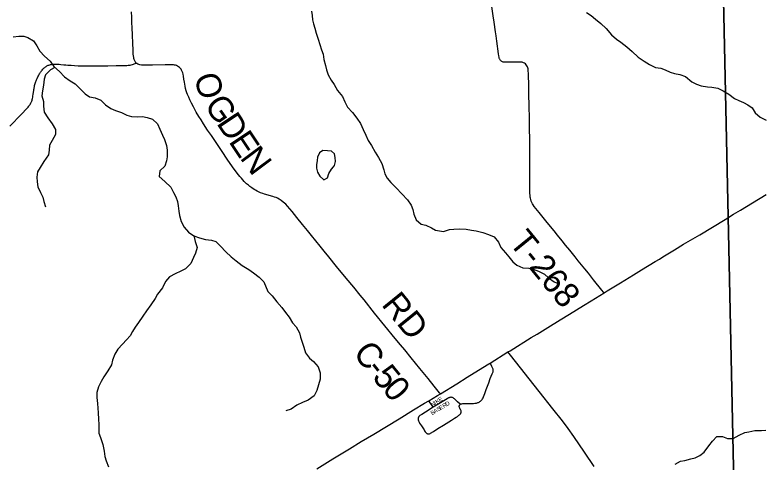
# Model space of a CAD drawing. Extents: x 1442749 to 1756758, y 235267 to 677782.
# Drawn here: x 1568709 to 1577781, y 515411 to 520821 of the extents above; entities that cross this region are included whole.
import ezdxf

# ---------------------------------------------------------------- set-up
doc = ezdxf.new("R2010")
doc.units = 0
for name, color, linetype in [('GM_X_County_Road', 7, 'Continuous'), ('GM_X_County_Road_Text', 7, 'Continuous'), ('GM_X_County_Subdivision', 7, 'Continuous'), ('GM_X_County_Subdivision_Text', 7, 'Continuous'), ('GM_X_Minor_Lake', 7, 'Continuous'), ('GM_X_Minor_River', 7, 'Continuous'), ('GM_X_State_Route', 7, 'Continuous'), ('GM_X_Township', 7, 'Continuous'), ('GM_X_Township_Road', 7, 'Continuous'), ('GM_X_Township_Road_Text', 7, 'Continuous')]:
    doc.layers.add(name, color=color, linetype=linetype)

msp = doc.modelspace()

# ---------------------------------------------------------------- linework, layer by layer
at = {"layer": 'GM_X_County_Road'}
for points in [[(1570179.2, 520236.9), (1570171.9, 520243.8), (1570162.8, 520256.4), (1570154.4, 520273.3), (1570150.9, 520282.3), (1570147.6, 520294.4), (1570145, 520307.3), (1570142.2, 520325.7), (1570140.5, 520346.1), (1570139.1, 520367.3), (1570137, 520409.6), (1570135, 520462.3), (1570133.4, 520500.4), (1570131.2, 520557), (1570129.7, 520588.2), (1570127, 520657.2), (1570123.7, 520739.7), (1570121.5, 520795.9), (1570119.3, 520857.7)], [(1573854.6, 516237.1), (1573845.8, 516247.9), (1573781.4, 516327.4), (1573705.3, 516421.3), (1573605.6, 516544), (1573553.3, 516608.4), (1573501.3, 516672), (1573423.8, 516767), (1573371.8, 516830.2), (1573308.8, 516905.8), (1573184.9, 517058.7), (1573059.9, 517214), (1572931.5, 517373.7), (1572884.3, 517431.4), (1572808.1, 517526), (1572715, 517637.9), (1572599.8, 517776.5), (1572503.8, 517895.7), (1572450.7, 517962.5), (1572401.5, 518024), (1572297.8, 518150.8), (1572248.5, 518212.1), (1572188.9, 518285.6), (1572120.4, 518370), (1572062.3, 518442), (1572035.5, 518473.7), (1572006.2, 518506.8), (1571984.3, 518530.5), (1571954.9, 518557.4), (1571928.4, 518577.4), (1571902.8, 518593), (1571884.8, 518602.5), (1571867.5, 518610.5), (1571848.7, 518617.8), (1571829.6, 518624.1), (1571812.3, 518629.2), (1571772.8, 518640), (1571729.1, 518652.5), (1571709, 518658.7), (1571678.5, 518669.8), (1571655.9, 518679.5), (1571638.9, 518687.8), (1571617.1, 518699.6), (1571600.4, 518709), (1571573, 518727.7), (1571551.9, 518743.7), (1571532.8, 518760), (1571511.3, 518779.7), (1571482.5, 518807.5), (1571447.5, 518844.9), (1571429.1, 518865.3), (1571412.5, 518886.9), (1571385.1, 518922.9), (1571341.8, 518982.3), (1571276.9, 519076.6), (1571215.3, 519168.1), (1571166.7, 519239.9), (1571084.3, 519361.6), (1571038.6, 519429.1), (1570990.1, 519504.1), (1570959.6, 519551.2), (1570934, 519593.1), (1570902.7, 519646.8), (1570868.1, 519709.7), (1570844.1, 519755.6), (1570824.3, 519795.8), (1570810.1, 519826.3), (1570797.3, 519858.2), (1570788.8, 519880.8), (1570781.7, 519901.2), (1570773.4, 519930.7), (1570766.4, 519960.9), (1570762.2, 519984.5), (1570758.1, 520009.1), (1570752.5, 520044.8), (1570746.7, 520081.2), (1570742.1, 520106.2), (1570738, 520121.4), (1570732.1, 520138.4), (1570724.8, 520153), (1570718.2, 520164.1), (1570708.9, 520176.6), (1570697.4, 520186.6), (1570686, 520195.4), (1570673.8, 520203.3), (1570663.8, 520207.8), (1570651.3, 520212), (1570638.5, 520215.1), (1570626.7, 520217.1), (1570614.2, 520217.8), (1570590.6, 520218.5), (1570561.5, 520218.9), (1570525.8, 520218.2), (1570374.5, 520215.4), (1570301, 520214), (1570264.3, 520214.4), (1570239, 520215.1), (1570220.3, 520216.8), (1570206.4, 520220.6), (1570196.1, 520225.1), (1570183, 520233.3), (1570179.2, 520236.9)], [(1575715.5, 515358.6), (1575599, 515528.7), (1575468.3, 515720.9), (1575399.6, 515816.9), (1575330, 515908.4), (1575214, 516055), (1575049.4, 516263.6), (1574702.5, 516704.5), (1574672.5, 516742.7)], [(1573768.5, 516072.9), (1573754.5, 516094.2), (1573723.7, 516141.1), (1573715.7, 516153.2)]]:
    msp.add_lwpolyline(points, dxfattribs=at)
at = {"layer": 'GM_X_County_Subdivision'}
for points in [[(1573768.5, 516072.9), (1573676.6, 516016.1), (1573629.2, 515987.5), (1573616, 515979.5), (1573607.8, 515973.9), (1573602.2, 515969.6), (1573597.4, 515965.2), (1573593, 515959.6), (1573590.9, 515956.1), (1573588.7, 515950.9), (1573587, 515946.6), (1573585.7, 515940.5), (1573585.2, 515936.1), (1573584.8, 515930.5), (1573585.2, 515924.9), (1573586.5, 515919.1), (1573588.3, 515913.1), (1573590.5, 515907.5), (1573593.5, 515901), (1573597.4, 515893.6), (1573603.4, 515883.2), (1573624.4, 515850.3), (1573656.8, 515798.9), (1573664.2, 515787.3), (1573671.5, 515776.3), (1573677.7, 515768.6), (1573682.7, 515763), (1573686.4, 515759.9), (1573689.8, 515757.3), (1573693.7, 515755.2), (1573699, 515753), (1573704.2, 515751.7), (1573708.9, 515751.3), (1573716.1, 515752.1), (1573722, 515753.9), (1573729.8, 515756.9), (1573736.3, 515760.4), (1573772.8, 515781.8), (1573825.7, 515814.9), (1573892.7, 515855.9), (1573926.4, 515876.7), (1573988.5, 515916.2), (1574026.2, 515940), (1574045.1, 515952.8), (1574060.5, 515963.5), (1574080, 515977.8), (1574087.4, 515983.9), (1574093.2, 515989), (1574097.8, 515994.7), (1574100.9, 515999.5), (1574102.9, 516004.3), (1574104.8, 516009.9), (1574105.4, 516015), (1574105.5, 516022.2), (1574104.5, 516029.4), (1574102.2, 516036.4), (1574098.7, 516045.1), (1574095.2, 516051.9), (1574090, 516062), (1574087, 516068.9), (1574084.8, 516075.1), (1574083.7, 516080.2), (1574083.5, 516084.6), (1574083.9, 516089.4), (1574085.2, 516093.7), (1574087.8, 516098.9), (1574091.7, 516104.5), (1574095.6, 516109.4), (1574100, 516111.9), (1574106.9, 516115), (1574113.5, 516116.7), (1574124.7, 516117.9), (1574235.4, 516120.2), (1574254.9, 516121), (1574270.1, 516121.9), (1574282.7, 516123.2), (1574292.5, 516125), (1574300.5, 516126.7), (1574309.6, 516129.7), (1574317, 516132.8), (1574324.4, 516136.7), (1574332.6, 516141.5), (1574340.5, 516147.1), (1574347.8, 516153.6), (1574353.4, 516159.7), (1574359.1, 516167), (1574365.5, 516177.4), (1574370.4, 516186.1), (1574376.4, 516198.2), (1574385.1, 516218.7), (1574393.3, 516241.2), (1574409.6, 516287.7), (1574439.4, 516368), (1574459, 516419.8), (1574481.5, 516477), (1574488, 516492.6), (1574491.9, 516503), (1574493.7, 516509.5), (1574494.5, 516517.3), (1574494.5, 516526), (1574493.7, 516533.8), (1574491, 516541.6), (1574486.7, 516550.7), (1574478, 516566.4), (1574463.3, 516593.3), (1574455.5, 516607.5)], [(1574095.6, 516109.4), (1574062.7, 516140.5), (1574033.6, 516168.4), (1574024.9, 516176.2), (1574018.4, 516181.4), (1574013.2, 516185.3), (1574007.5, 516188.3), (1574001, 516191.4), (1573994.3, 516193.2), (1573987.2, 516194.3), (1573979.8, 516194.8), (1573973, 516193.8), (1573965.9, 516192.2), (1573959.8, 516189.6), (1573954.2, 516187), (1573947.5, 516183.7), (1573935.9, 516176.6), (1573855.1, 516126.4), (1573768.5, 516072.9)]]:
    msp.add_lwpolyline(points, dxfattribs=at)
at = {"layer": 'GM_X_Minor_Lake'}
for points in [[(1572560.2, 518983.6), (1572573.6, 519000.2), (1572586.6, 519048), (1572581.5, 519096.2), (1572574.5, 519142.4), (1572537.1, 519173.2), (1572489.2, 519178.2), (1572433.3, 519181.3), (1572390.7, 519154.1), (1572369.6, 519102.4), (1572364.7, 519058.4)], [(1572364.7, 519058.4), (1572357.7, 519008.5), (1572354.8, 518966.5), (1572369.9, 518918.1), (1572396.9, 518871.5), (1572446, 518826.4), (1572488.5, 518849.6), (1572505.5, 518901.4), (1572538.7, 518956.8), (1572560.2, 518983.6)]]:
    msp.add_lwpolyline(points, dxfattribs=at)
at = {"layer": 'GM_X_Minor_River'}
for points in [[(1572297.8, 520868.8), (1572304.7, 520816.6), (1572307.6, 520764.4), (1572318.6, 520714.1), (1572335.5, 520659.7), (1572352.3, 520601.3), (1572374.8, 520526.7), (1572395.5, 520464.2), (1572418.2, 520397.6), (1572435.1, 520345.2), (1572445.8, 520282.9), (1572464.3, 520210.4), (1572477.2, 520156), (1572496, 520097.6), (1572534.7, 520032.7), (1572569.6, 519977.9), (1572610.1, 519907), (1572670.7, 519835.7), (1572697.3, 519769), (1572732.1, 519706.2), (1572792.7, 519640.9), (1572843.4, 519573.8), (1572888, 519506.8), (1572920.5, 519434.1), (1572953.2, 519367.3), (1572979.8, 519302.7), (1573022.6, 519239.7), (1573065, 519162.8), (1573107.7, 519097.8), (1573146.1, 519022.9), (1573172.6, 518948.3), (1573183.6, 518898), (1573212.5, 518845.3), (1573255.4, 518792.4), (1573318.1, 518729), (1573388.6, 518655.5), (1573457.2, 518586), (1573499.9, 518519.1), (1573520.8, 518466.6), (1573533.6, 518410.2), (1573560.3, 518343.6), (1573623.2, 518290.3), (1573677, 518279.2), (1573746.3, 518243.8), (1573797.7, 518216.7), (1573891.5, 518202.8), (1573963.9, 518223.4), (1574016, 518230.4), (1574092.1, 518234.9), (1574168, 518227.4), (1574229.8, 518218.2), (1574287.6, 518209), (1574369.2, 518187.4), (1574438.8, 518165.9), (1574504.1, 518134.6), (1574556.9, 518073.5), (1574587.6, 518008.8), (1574642.3, 517943.6), (1574683.2, 517892.7), (1574730.1, 517835.6), (1574781.2, 517794.6), (1574852.5, 517761.1), (1574924.5, 517757.7), (1574978.3, 517746.6), (1575039.8, 517721.3), (1575113, 517683.8), (1575164.1, 517640.8), (1575229.2, 517593.4), (1575294.5, 517562)], [(1575622, 520853), (1575679.2, 520815.8), (1575730.3, 520768.8), (1575797.2, 520717.3), (1575860, 520658), (1575924.5, 520582.6), (1575985.4, 520527.3), (1576036.7, 520492.2), (1576109.5, 520436.7), (1576174.3, 520377.3), (1576247, 520311.8), (1576320.1, 520264.2), (1576383.2, 520222.9), (1576456.5, 520187.4), (1576522.3, 520176.1), (1576573.9, 520157), (1576633.4, 520129.8), (1576687.1, 520114.7), (1576750.8, 520101.5), (1576820.3, 520078), (1576896.9, 520010.4), (1576952.4, 519983.3), (1577008, 519964.1), (1577087.8, 519950.5), (1577139.7, 519947.5), (1577211.5, 519936.1), (1577274.8, 519902.8), (1577344, 519861.3), (1577411, 519811.9), (1577464.4, 519784.8), (1577520, 519761.7), (1577573.4, 519734.6), (1577624.6, 519695.5), (1577661.5, 519638.7), (1577724.4, 519585.3), (1577795.6, 519547.9)], [(1568686.8, 520557.7), (1568757, 520566.3), (1568814.9, 520563.2), (1568866.6, 520548.1), (1568931.8, 520506.8), (1568972.6, 520449.8), (1569009.3, 520383), (1569066, 520321.8), (1569132.8, 520262.4), (1569179.5, 520197.3), (1569246.3, 520137.9), (1569307, 520074.6), (1569378, 520025.1), (1569437.3, 519987.9), (1569494.1, 519930.7), (1569558.8, 519867.3), (1569612.1, 519832.2), (1569679.8, 519816.8), (1569749.3, 519789.4), (1569802.1, 519734.2), (1569867.2, 519688.9), (1569926.8, 519665.6), (1569996.3, 519640.2), (1570063.6, 519608.9), (1570117.3, 519593.8), (1570195.3, 519590.2), (1570251.3, 519593.1), (1570307.1, 519582), (1570370.6, 519558.7), (1570431.6, 519505.4), (1570462.2, 519438.7), (1570492.8, 519368), (1570517.7, 519313.4), (1570542.2, 519240.8), (1570549.1, 519186.5)], [(1569192.8, 520185.5), (1569138.7, 520156.1), (1569079.4, 520097.1), (1569062.3, 520043.4), (1569054.9, 519973.4), (1569041.5, 519903.6), (1569034.2, 519841.6), (1569052.8, 519773.1), (1569053.7, 519717), (1569064.2, 519646.7), (1569106.8, 519575.7), (1569159.3, 519504.6), (1569197.9, 519435.7), (1569198.7, 519373.6), (1569157.2, 519300.3), (1569128, 519246.8), (1569122.8, 519184.7), (1569113.6, 519126.8), (1569060, 519047.8), (1569012.5, 518974.6), (1568981.4, 518923.1), (1568972, 518857.2), (1568976.9, 518803), (1568983.7, 518740.8), (1569016.3, 518674), (1569047.1, 518615.3), (1569060.1, 518565), (1569076.7, 518498.5)], [(1570549.1, 519186.5), (1570549.4, 519106.4), (1570540.4, 519054.5), (1570523, 518990.7), (1570459.9, 518935.9), (1570452.5, 518865.9), (1570523.2, 518804.4), (1570593.9, 518736.9), (1570628.6, 518674.1), (1570655.5, 518621.5), (1570676.4, 518565), (1570681.2, 518510.8), (1570692, 518448.5), (1570698.9, 518394.3), (1570719.4, 518321.8), (1570756, 518252.9), (1570806.7, 518191.8), (1570873.9, 518150.4), (1570941.4, 518125), (1571013, 518105.6), (1571084.8, 518096.1), (1571138.5, 518081.1), (1571193.3, 518021.9), (1571257.9, 517954.5), (1571322.7, 517895.1), (1571385.7, 517845.8), (1571456.6, 517788.3), (1571537.6, 517742.6), (1571594.8, 517699.4), (1571661.7, 517648), (1571718.6, 517592.8), (1571768.2, 517475.6), (1571819.1, 517422.5), (1571877.7, 517351.2), (1571936.3, 517282), (1571981, 517219), (1572025.9, 517164), (1572066.5, 517097.1), (1572109.5, 517046.2), (1572150, 516975.3), (1572162.9, 516922.9), (1572183.7, 516860.4), (1572202.5, 516801.9), (1572225.1, 516733.4), (1572269.7, 516666.4), (1572320.9, 516627.3), (1572377.6, 516562.1), (1572400.1, 516489.5), (1572402.5, 516413.3), (1572381.1, 516345.7), (1572361.7, 516277.9), (1572326.3, 516210.5), (1572255.3, 516159.8), (1572188.7, 516133.1), (1572120, 516098.4), (1572051.1, 516051.7), (1571984.6, 516029)], [(1570870.9, 518152.3), (1570888.5, 518080), (1570911, 518007.4), (1570893.5, 517937.7), (1570868.5, 517886.1), (1570837, 517812.6), (1570773.7, 517749.7), (1570715.1, 517720.8), (1570646.4, 517688.1), (1570577.6, 517651.4), (1570530.4, 517594.3), (1570492.9, 517518.9), (1570431.3, 517444), (1570406.2, 517388.4), (1570352.6, 517313.3), (1570301.2, 517242.2), (1570255.8, 517175), (1570202.3, 517100), (1570163.1, 517044.6), (1570130, 516991.2), (1570100.9, 516939.7), (1570059.9, 516888.4), (1570008.8, 516835.4), (1569951.6, 516776.4), (1569916.3, 516715), (1569886.8, 516643.5), (1569875.7, 516587.6), (1569832.2, 516516.3), (1569784.7, 516443.2), (1569751.5, 516385.7), (1569718.2, 516322.3), (1569700.8, 516252.5), (1569697.5, 516190.5), (1569706, 516118.2), (1569710.9, 516062), (1569713.7, 516005.8), (1569720.2, 515931.6), (1569722.9, 515865.4), (1569721.8, 515811.4), (1569724.7, 515759.2), (1569743.6, 515708.8), (1569771.9, 515622.1), (1569786.3, 515543.7), (1569797, 515479.3), (1569811.8, 515425), (1569840.4, 515354.3)], [(1576696.1, 515386.8), (1576760.8, 515419.6), (1576813.1, 515430.6), (1576885.5, 515451.2), (1576937.7, 515462.2), (1576992.3, 515489.1), (1577045.2, 515532.2), (1577100.7, 515605.2), (1577147.9, 515662.3), (1577199, 515719.4), (1577269, 515718), (1577328.6, 515696.8), (1577394.6, 515697.5), (1577467.4, 515734.1), (1577536.1, 515768.8), (1577586.3, 515777.9), (1577658.6, 515792.5), (1577738.6, 515792.9), (1577790.7, 515797.9)]]:
    msp.add_lwpolyline(points, dxfattribs=at)
at = {"layer": 'GM_X_State_Route'}
msp.add_lwpolyline([(1572359.8, 515329.4), (1572552.6, 515447.9), (1572754.5, 515570.6), (1572897.1, 515658.1), (1573048.6, 515749.9), (1573354.3, 515935.4), (1573531.4, 516041.9), (1573663.4, 516121.7), (1573715.7, 516153.2), (1573820.8, 516216.5), (1573854.6, 516237.1), (1574053.1, 516358.4), (1574178.1, 516437.2), (1574264.5, 516490.7), (1574440.9, 516598.4), (1574455.5, 516607.5), (1574672.5, 516742.7), (1574697, 516758), (1574953.9, 516916.4), (1575023.9, 516958.9), (1575156.1, 517038.4), (1575303.7, 517130.3), (1575415.4, 517199.1), (1575585.7, 517304), (1575678.2, 517360.2), (1575835.1, 517458), (1575873.1, 517481.8), (1576032.3, 517579.8), (1576191.4, 517677.8), (1576289.2, 517737.7), (1576451.8, 517836.6), (1576503.4, 517867.9), (1576547.3, 517894.5), (1576687.5, 517979.4), (1576796.9, 518045.7), (1576991.3, 518161.5), (1577297.6, 518346.2), (1577332.3, 518367.4), (1577401.1, 518409.6), (1577485.3, 518460.4), (1577630.8, 518549), (1577795.5, 518650.4)], dxfattribs=at)
at = {"layer": 'GM_X_Township'}
for points in [[(1566007.1, 539894.4), (1574567.9, 539458.5), (1575500.4, 539411), (1576764.1, 539348.5), (1576884.4, 539342.6), (1576886.4, 539252.1), (1577095.4, 529536.7), (1577246.7, 522507.3), (1577335.5, 518378.1), (1577466, 512312.2), (1577284.9, 512328.8), (1572224.6, 512792.5), (1572116.5, 513572.1), (1570495.5, 513586.9), (1570073.6, 513943.9), (1565959.1, 517425.5)], [(1607409.4, 509023.5), (1601348.8, 509660.4), (1598207.2, 509990.6), (1595438.2, 510291.2), (1595354.9, 510300.2), (1591669.6, 510700.6), (1587291.5, 511155.9), (1584740.5, 511410.2), (1583704.9, 511521.1), (1580872.9, 511824.8), (1577466, 512312.2), (1577335.5, 518378.1), (1577246.7, 522507.3)]]:
    msp.add_lwpolyline(points, dxfattribs=at)
at = {"layer": 'GM_X_Township_Road'}
for points in [[(1575835.1, 517458), (1575827.4, 517467.6), (1575808.8, 517490.8), (1575706.9, 517617.5), (1575644.7, 517694.8), (1575600.3, 517750), (1575543.1, 517821.9), (1575522.5, 517847.5), (1575483.2, 517895.7), (1575419.3, 517974.8), (1575369.3, 518036.8), (1575328.6, 518087.2), (1575272.7, 518155.9), (1575230, 518209.1), (1575187.6, 518261.3), (1575130.8, 518331), (1575048.3, 518431.4), (1575009.8, 518478.3), (1574989, 518504.3), (1574975.7, 518523.6), (1574967.6, 518537.1), (1574961.3, 518550), (1574953.4, 518569.5), (1574947.2, 518589.2), (1574943.8, 518604), (1574941.4, 518617.9), (1574939.5, 518635), (1574938.1, 518665.2), (1574937.4, 518695.1), (1574935.2, 519011.5), (1574935.4, 519129), (1574935.6, 519247.6), (1574932.8, 519516.5), (1574931.4, 519595.3), (1574929.3, 519694.7), (1574925.2, 519892.4), (1574924.1, 519945.8), (1574919.1, 520122.6), (1574918.4, 520137.7), (1574917.1, 520154.3), (1574915.5, 520167.9), (1574912.6, 520179.8), (1574907.9, 520193.2), (1574901.4, 520206.2), (1574893.8, 520216.8), (1574883.4, 520228.2), (1574871, 520237.5), (1574861.8, 520242.5), (1574851.9, 520246.2), (1574842.7, 520248.7), (1574831.4, 520251), (1574819.9, 520251.6), (1574807.3, 520252), (1574745.2, 520251.4), (1574676.4, 520249), (1574639.8, 520249), (1574621.8, 520250.6), (1574614.5, 520252), (1574607.6, 520254.2), (1574599.9, 520257.8), (1574593.7, 520261.2), (1574586.2, 520267), (1574581.9, 520271.4), (1574576.9, 520278.4), (1574573.2, 520284.9), (1574570.8, 520291.3), (1574567.8, 520299.5), (1574564.7, 520311.6), (1574561.3, 520328.3), (1574557.4, 520351.6), (1574538.1, 520502.5), (1574533.5, 520536.4), (1574529.4, 520567.2), (1574521.9, 520615.5), (1574504.3, 520735.5), (1574492.7, 520812.7), (1574476.1, 520922.6)], [(1568648.6, 519476), (1568787.9, 519621.9), (1568851.7, 519689.1), (1568867.8, 519706.9), (1568877.3, 519718.2), (1568882.5, 519724.7), (1568888.1, 519732.1), (1568892.5, 519738.6), (1568897.7, 519747.7), (1568902, 519756), (1568906, 519764.6), (1568908.8, 519771.2), (1568912, 519778.6), (1568915.5, 519789), (1568917.7, 519798.1), (1568920.6, 519811), (1568923.3, 519824.6), (1568926, 519840.2), (1568929.3, 519863.9), (1568935.4, 519908.3), (1568937.2, 519921.3), (1568939.3, 519932.2), (1568941.1, 519941.7), (1568943.3, 519953.5), (1568946.7, 519969.1), (1568949.8, 519981.2), (1568952.8, 519993.4), (1568956.3, 520004.2), (1568959.8, 520014.6), (1568964.2, 520025.9), (1568968.9, 520038.1), (1568976.3, 520054.1), (1568984.9, 520071.5), (1568991.9, 520084.1), (1568996.7, 520093.2), (1569002, 520102.5), (1569007.5, 520112.3), (1569012.7, 520120.5), (1569017.9, 520128.4), (1569024.4, 520137.5), (1569030.5, 520145.7), (1569036.2, 520153.6), (1569045.7, 520165.3), (1569053.9, 520173.9), (1569060.9, 520180.8), (1569068.7, 520187.4), (1569077.4, 520193.9), (1569086.1, 520199.6), (1569094.7, 520204.3), (1569103, 520208.7), (1569111.2, 520212.6), (1569119.9, 520215.6), (1569129, 520218.2), (1569139, 520220.8), (1569150.7, 520223), (1569162.9, 520224.7), (1569177.2, 520226), (1569194.1, 520226.5), (1569211.9, 520226), (1569224.2, 520225.5), (1569242.3, 520224.3), (1569264.4, 520222.5), (1569299.2, 520219.5), (1569323.4, 520217.4), (1569348.2, 520215.2), (1569389, 520212.1), (1569431.1, 520209.5), (1569473.2, 520207.4), (1569508.4, 520206), (1569535.7, 520205.6), (1569569.6, 520205.2), (1569617.3, 520205.2), (1569668.5, 520205.2), (1569716.3, 520205.2), (1569767, 520205.6), (1569832.6, 520206.9), (1569932, 520208.7), (1569993.2, 520209.6), (1570036.6, 520210.4), (1570062.6, 520211.3), (1570079.1, 520212.6), (1570091.7, 520213.9), (1570102.1, 520215.6), (1570113.4, 520218.2), (1570132.1, 520222.5), (1570163.4, 520232.1), (1570179.2, 520236.9)]]:
    msp.add_lwpolyline(points, dxfattribs=at)

# ---------------------------------------------------------------- texts
at = {"layer": 'GM_X_County_Road_Text'}
for s, rotation, p in [('O', 286.52132, (1570870.1, 520073.4)), ('G', 304.85373, (1570990.5, 519726.3)), ('D', 303.68603, (1571140.4, 519511)), ('E', 303.71445, (1571286.9, 519291.1)), ('N', 306.80421, (1571421.7, 519090.1)), ('RD', 309.03698, (1573133.4, 517313.9)), ('C', 308.74363, (1572788.2, 516725.5)), ('-', 308.83062, (1572942.8, 516532.9)), ('5', 309.1386, (1573021.1, 516435.6)), ('0', 310.18449, (1573141.6, 516287.6))]:
    msp.add_text(s, height=300, rotation=rotation, dxfattribs=at).set_placement(p)
at = {"layer": 'GM_X_County_Subdivision_Text'}
for s, rotation, p in [('E', 32.20558, (1573849.5, 516137.3)), ('N', 31.10058, (1573755.1, 516078.9)), ('I', 32.13607, (1573793.6, 516102.1)), ('K', 32.18322, (1573812.3, 516113.9)), ('E', 31.31753, (1573856.6, 516038.9)), ('R', 31.18162, (1573898, 516064)), ('D', 31.18675, (1573931.9, 516084.6)), ('B', 33.44082, (1573756.8, 515975.4)), ('A', 32.22895, (1573789.7, 515997.1)), ('S', 31.69698, (1573826.8, 516020.5))]:
    msp.add_text(s, height=50, rotation=rotation, dxfattribs=at).set_placement(p)
at = {"layer": 'GM_X_Township_Road_Text'}
msp.add_text('T-268', height=300, rotation=309.21228, dxfattribs=at).set_placement((1574674.7, 518064.3))

doc.saveas('drawing.dxf')
